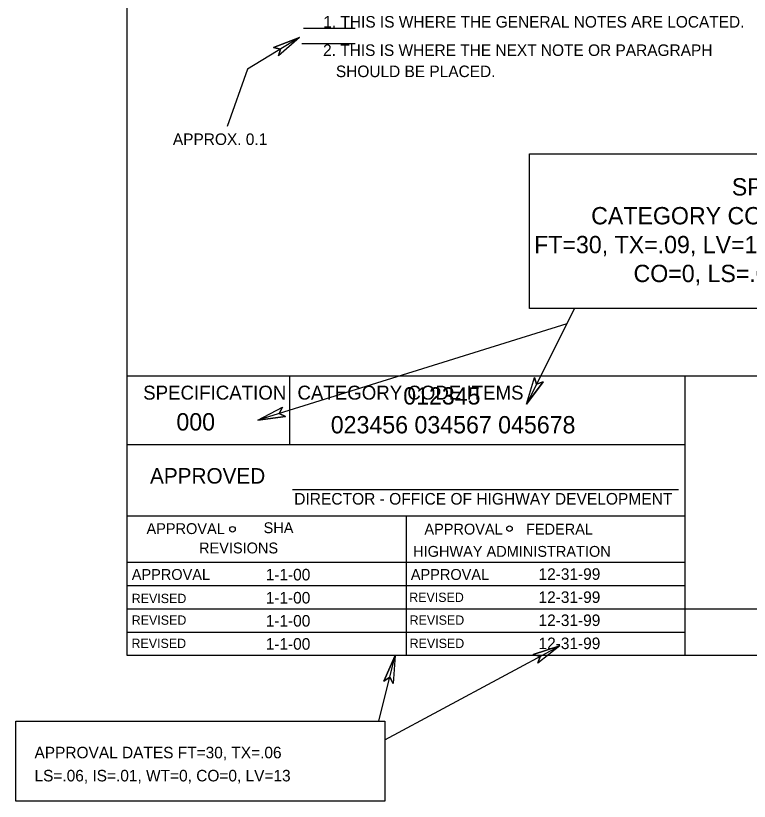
# Model space of a CAD drawing. Extents: x -0.5 to 19.9, y 5.2 to 17.3.
# Drawn here: x -0.185 to 3.628, y 5.179 to 9.261 of the extents above; entities that cross this region are included whole.
import ezdxf

# ---------------------------------------------------------------- set-up
doc = ezdxf.new("R2010")
doc.units = 0
for name, color, linetype in [('BORD-LINE', 7, 'Continuous'), ('DETL-DIMS', 7, 'Continuous'), ('DETL-NOTE', 7, 'Continuous'), ('TTLB-TEXT', 7, 'Continuous'), ('USER-BORD', 7, 'Continuous')]:
    doc.layers.add(name, color=color, linetype=linetype)

msp = doc.modelspace()

# ---------------------------------------------------------------- linework, layer by layer
at = {"layer": 'BORD-LINE'}
for p, q in [((7.7685, 7.3883), (0.3943, 7.3883)), ((1.2535, 6.7985), (3.2604, 6.7985)), ((0.3943, 6.6629), (1.2405, 6.6629)), ((0.3943, 5.9375), (0.3943, 6.6629)), ((1.2405, 6.0584), (3.2956, 6.0584))]:
    msp.add_line(p, q, dxfattribs=at)
at = {"layer": 'DETL-DIMS'}
for p, q in [((1.2901, 9.1483), (1.0203, 8.9841)), ((1.2901, 9.1483), (1.1548, 9.0955)), ((1.2901, 9.1483), (1.181, 9.0524)), ((1.1548, 9.0955), (1.191, 9.088)), ((1.191, 9.088), (1.181, 9.0524)), ((1.0203, 8.9841), (0.9148, 8.6849)), ((2.7192, 7.74), (2.4706, 7.2422)), ((2.6792, 7.6599), (1.0734, 7.16)), ((2.4706, 7.2422), (2.512, 7.3814)), ((2.4706, 7.2422), (2.557, 7.3589)), ((2.5224, 7.346), (2.512, 7.3814)), ((2.557, 7.3589), (2.5224, 7.346)), ((1.0734, 7.16), (1.2024, 7.2266)), ((1.1842, 7.1945), (1.2024, 7.2266)), ((1.2174, 7.1784), (1.1842, 7.1945)), ((1.0734, 7.16), (1.2174, 7.1784)), ((1.7345, 5.4977), (2.6438, 5.9866)), ((2.6438, 5.9866), (2.5059, 5.9411)), ((2.6438, 5.9866), (2.5298, 5.8967)), ((1.7034, 5.5961), (1.7884, 5.9359)), ((1.7884, 5.9359), (1.7293, 5.8033)), ((1.7884, 5.9359), (1.7782, 5.7911)), ((2.5059, 5.9411), (2.5416, 5.9317)), ((2.5416, 5.9317), (2.5298, 5.8967)), ((1.7293, 5.8033), (1.7603, 5.8234)), ((1.7603, 5.8234), (1.7782, 5.7911))]:
    msp.add_line(p, q, dxfattribs=at)
for points in [[(1.1548, 9.0955), (1.2901, 9.1483), (1.181, 9.0524), (1.191, 9.088)], [(2.557, 7.3589), (2.4706, 7.2422), (2.512, 7.3814), (2.5224, 7.346)], [(1.2174, 7.1784), (1.0734, 7.16), (1.2024, 7.2266), (1.1842, 7.1945)], [(2.5059, 5.9411), (2.6438, 5.9866), (2.5298, 5.8967), (2.5416, 5.9317)], [(1.7293, 5.8033), (1.7884, 5.9359), (1.7782, 5.7911), (1.7603, 5.8234)]]:
    msp.add_lwpolyline(points, close=True, dxfattribs=at)
at = {"layer": 'DETL-NOTE'}
for p, q in [((1.3106, 9.1971), (1.5804, 9.1971)), ((1.3018, 9.1171), (1.5804, 9.1171))]:
    msp.add_line(p, q, dxfattribs=at)
for centre in [(0.9422, 6.5926), (2.3819, 6.5959)]:
    msp.add_ellipse(centre, major_axis=(0, -0.0143), ratio=0.999903, dxfattribs=at)
at = {"layer": 'TTLB-TEXT'}
msp.add_line((7.7685, 7.3883), (0.3943, 7.3883), dxfattribs=at)
for points in [[(0.3943, 16.2906), (7.7685, 16.2906), (7.7685, 5.9375), (0.3943, 5.9375)], [(2.4865, 8.5442), (4.7055, 8.5442), (4.7055, 7.74), (2.4865, 7.74)], [(-0.1847, 5.5961), (1.7345, 5.5961), (1.7345, 5.1791), (-0.1847, 5.1791)]]:
    msp.add_lwpolyline(points, close=True, dxfattribs=at)
for centre in [(0.9422, 6.5926), (2.3819, 6.5959)]:
    msp.add_ellipse(centre, major_axis=(0, -0.0143), ratio=0.999903, dxfattribs=at)
at = {"layer": 'USER-BORD'}
for p, q in [((7.7685, 7.3883), (0.3943, 7.3883)), ((1.2405, 7.0336), (1.2405, 7.3883)), ((3.2956, 5.9375), (3.2956, 7.3883)), ((0.3943, 7.0336), (3.2956, 7.0336)), ((0.3943, 6.6629), (3.2956, 6.6629)), ((1.8449, 6.6629), (1.8449, 5.9375)), ((0.3943, 6.4211), (3.2956, 6.4211)), ((0.3943, 6.3002), (3.2956, 6.3002)), ((0.3943, 6.1793), (3.2956, 6.1793)), ((3.2956, 6.1793), (7.7685, 6.1793)), ((0.3943, 6.0584), (3.2956, 6.0584))]:
    msp.add_line(p, q, dxfattribs=at)

# ---------------------------------------------------------------- texts
at = {"layer": 'DETL-NOTE'}
for s, height, p in [('1. THIS IS WHERE THE GENERAL NOTES ARE LOCATED.', 0.06, (1.4142, 9.1994)), ('2. THIS IS WHERE THE NEXT NOTE OR PARAGRAPH', 0.06, (1.4129, 9.0521)), ('   SHOULD BE PLACED.', 0.06, (1.4129, 8.9421)), ('APPROX. 0.1', 0.06, (0.6324, 8.5895)), ('CATEGORY CODE ITEMS ', 0.07254, (1.2798, 7.2662))]:
    msp.add_text(s, height=height, dxfattribs=at).set_placement(p)
at = {"layer": 'TTLB-TEXT'}
for s, height, p in [('SPECIFICATION,', 0.09, (3.5376, 8.327)), (' CATEGORY CODE ITEMS, ', 0.09, (2.7731, 8.177)), ('FT=30, TX=.09, LV=13, WT=0,', 0.09, (2.5102, 8.027)), (' CO=0, LS=.06, IS=.01', 0.09, (2.9933, 7.877)), ('SPECIFICATION', 0.07254, (0.4779, 7.2662)), ('CATEGORY CODE ITEMS ', 0.07254, (1.2798, 7.2662)), ('            012345', 0.09, (1.4285, 7.2408)), ('000', 0.09, (0.6506, 7.1059)), ('023456 034567 045678', 0.09, (1.4531, 7.0908)), ('APPROVED', 0.0806, (0.5135, 6.8299)), ('DIRECTOR - OFFICE OF HIGHWAY DEVELOPMENT', 0.0604, (1.263, 6.7207)), ('APPROVAL', 0.05642, (0.4953, 6.5677)), ('SHA', 0.05642, (1.1039, 6.5724)), ('APPROVAL', 0.05642, (1.9398, 6.5652)), ('FEDERAL', 0.05642, (2.4679, 6.5653)), ('REVISIONS', 0.05642, (0.7684, 6.4672)), ('HIGHWAY ADMINISTRATION', 0.05642, (1.8813, 6.4495)), ('APPROVAL', 0.05642, (0.4187, 6.3295)), ('1-1-00', 0.06, (1.1148, 6.3268)), ('APPROVAL', 0.05642, (1.8693, 6.3295)), ('12-31-99', 0.06, (2.533, 6.3298)), ('1-1-00', 0.06, (1.1148, 6.2068)), ('12-31-99', 0.06, (2.533, 6.2098)), ('1-1-00', 0.06, (1.1148, 6.0868)), ('12-31-99', 0.06, (2.533, 6.0898)), ('1-1-00', 0.06, (1.1148, 5.9668)), ('12-31-99', 0.06, (2.533, 5.9698)), ('APPROVAL DATES FT=30, TX=.06', 0.06, (-0.087, 5.4024)), ('LS=.06, IS=.01, WT=0, CO=0, LV=13 ', 0.06, (-0.087, 5.2824))]:
    msp.add_text(s, height=height, dxfattribs=at).set_placement(p)
at = {"layer": 'USER-BORD'}
for s, height, p in [('DIRECTOR - OFFICE OF HIGHWAY DEVELOPMENT', 0.0604, (1.263, 6.7207)), ('REVISED', 0.04836, (0.4184, 6.209)), ('REVISED', 0.04836, (1.8606, 6.2149)), ('REVISED', 0.04836, (0.4184, 6.0964)), ('REVISED', 0.04836, (1.8629, 6.0964)), ('REVISED', 0.04836, (0.4171, 5.9756)), ('REVISED', 0.04836, (1.8629, 5.9756))]:
    msp.add_text(s, height=height, dxfattribs=at).set_placement(p)

doc.saveas('drawing.dxf')
